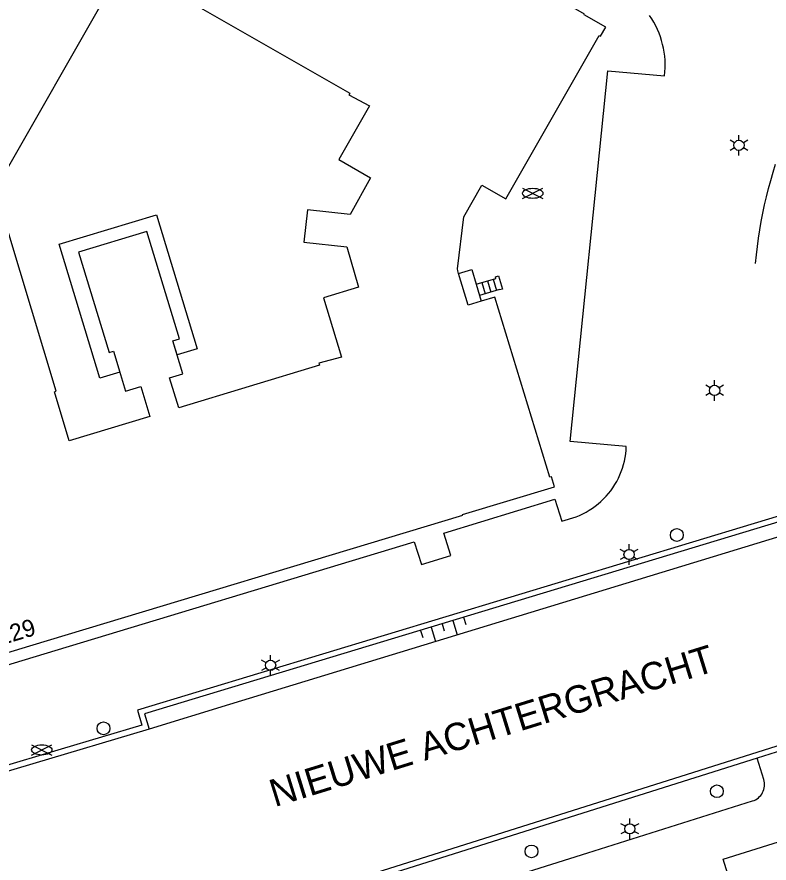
# Model space of a CAD drawing. Extents: x 122462 to 123306, y 485548 to 486417.
# Drawn here: x 122661.2 to 122727, y 486275.7 to 486349.8 of the extents above; entities that cross this region are included whole.
import ezdxf

# ---------------------------------------------------------------- set-up
doc = ezdxf.new("R2010")
doc.units = 0
for name, color, linetype in [('Level 1', 7, 'Continuous'), ('Level 10', 7, 'Continuous'), ('Level 15', 7, 'Continuous'), ('Level 17', 7, 'Continuous'), ('Level 30', 7, 'Continuous'), ('Level 31', 7, 'Continuous'), ('Level 33', 7, 'Continuous'), ('Level 50', 7, 'Continuous'), ('Level 52', 7, 'Continuous'), ('Level 53', 7, 'Continuous'), ('Level 57', 7, 'Continuous'), ('Level 58', 7, 'Continuous'), ('Level 60', 7, 'Continuous')]:
    doc.layers.add(name, color=color, linetype=linetype)

msp = doc.modelspace()

# ---------------------------------------------------------------- linework, layer by layer
at = {"layer": 'Level 1'}
for points in [[(122699.817, 486327.312), (122699.749, 486327.539), (122699.729, 486327.739), (122700.284, 486332.276), (122701.858, 486335.038), (122703.959, 486333.84), (122712.114, 486348.156), (122712.229, 486348.09), (122712.699, 486348.89), (122710.807, 486349.962), (122710.84, 486350.019), (122666.793, 486375.245)], [(122670.497, 486354.444), (122690.291, 486343.11), (122690.207, 486342.963), (122692.022, 486342.005), (122689.355, 486337.307), (122692.119, 486335.704), (122690.347, 486332.49), (122686.599, 486332.897), (122686.294, 486330.053), (122690.041, 486329.638), (122691.06, 486326.112), (122688.005, 486325.193), (122689.573, 486319.986), (122687.594, 486319.457), (122687.646, 486319.284), (122675.334, 486315.567), (122674.54, 486318.195), (122675.69, 486318.542), (122674.822, 486321.415), (122675.391, 486321.587), (122672.55, 486330.998), (122666.579, 486329.195), (122669.237, 486320.39), (122669.616, 486320.505), (122670.667, 486317.025), (122672.014, 486317.432), (122672.808, 486314.804), (122665.752, 486312.674)], [(122665.752, 486312.674), (122664.457, 486316.963), (122664.619, 486317.012), (122659.289, 486334.67), (122669.606, 486352.743)], [(122701.792, 486324.887), (122700.65, 486324.549), (122699.817, 486327.312)], [(122654.824, 486293.037), (122654.979, 486292.519), (122662.302, 486294.73), (122700.189, 486306.17), (122700.175, 486306.219), (122708.219, 486308.64), (122707.959, 486309.519), (122707.814, 486309.477), (122702.979, 486325.239), (122701.792, 486324.887)]]:
    msp.add_lwpolyline(points, dxfattribs=at)
at = {"layer": 'Level 10'}
msp.add_lwpolyline([(122668.431, 486318.142), (122664.882, 486329.891), (122673.401, 486332.464), (122676.949, 486320.715), (122675.194, 486320.185), (122674.822, 486321.415), (122675.391, 486321.587), (122672.55, 486330.998), (122666.579, 486329.195), (122669.237, 486320.39), (122669.616, 486320.505), (122670.171, 486318.668), (122668.431, 486318.142)], dxfattribs=at)
at = {"layer": 'Level 15'}
msp.add_line((122756.891, 486294.683), (122725.93, 486284.893), dxfattribs=at)
for points in [[(122751.923, 486312.872), (122672.34, 486288.76), (122672.74, 486287.44)], [(122731.082, 486307.081), (122671.716, 486289.094), (122672.116, 486287.776), (122665.051, 486285.671), (122641.584, 486278.678), (122641.891, 486277.59), (122640.687, 486277.213)], [(122647.698, 486260.681), (122684.849, 486272.428), (122757.048, 486295.256)], [(122672.74, 486287.44), (122642.199, 486278.339), (122642.372, 486277.724), (122642.388, 486277.64), (122642.389, 486277.555), (122642.376, 486277.47), (122642.348, 486277.389), (122642.308, 486277.314), (122642.255, 486277.247), (122642.191, 486277.19), (122642.119, 486277.145), (122642.04, 486277.112), (122640.835, 486276.735)], [(122725.93, 486284.893), (122710.139, 486279.9), (122647.848, 486260.204), (122647.698, 486260.681)]]:
    msp.add_lwpolyline(points, dxfattribs=at)
at = {"layer": 'Level 17'}
for points in [[(122655.079, 486291.467), (122662.602, 486293.74), (122695.944, 486303.816), (122696.584, 486301.838), (122699.14, 486302.645), (122698.525, 486304.593), (122708.241, 486307.555), (122708.852, 486305.625), (122710.108, 486306.026), (122710.404, 486306.147), (122710.695, 486306.281), (122710.978, 486306.429), (122711.255, 486306.59), (122711.523, 486306.764), (122711.783, 486306.951), (122712.034, 486307.149), (122712.276, 486307.359), (122712.507, 486307.58), (122712.728, 486307.812), (122712.937, 486308.053), (122713.135, 486308.305), (122713.321, 486308.565), (122713.495, 486308.834), (122713.655, 486309.111), (122713.803, 486309.394), (122713.937, 486309.685), (122714.057, 486309.981), (122714.163, 486310.283), (122714.255, 486310.59), (122714.332, 486310.9), (122714.395, 486311.214), (122714.443, 486311.53), (122714.476, 486311.849), (122714.494, 486312.168), (122709.597, 486312.611), (122712.877, 486345.066), (122717.835, 486344.614), (122717.871, 486344.959), (122717.89, 486345.306), (122717.894, 486345.653), (122717.882, 486346), (122717.854, 486346.346), (122717.81, 486346.691), (122717.75, 486347.033), (122717.675, 486347.372), (122717.584, 486347.707), (122717.478, 486348.038), (122717.357, 486348.363), (122717.222, 486348.683), (122717.071, 486348.996), (122716.907, 486349.302), (122716.728, 486349.6), (122716.537, 486349.889)], [(122725.812, 486328.204), (122725.882, 486328.94), (122725.966, 486329.674), (122726.064, 486330.406), (122726.176, 486331.137), (122726.301, 486331.865), (122726.439, 486332.591), (122726.591, 486333.314), (122726.757, 486334.034), (122726.936, 486334.751), (122727.128, 486335.464), (122727.334, 486336.174), (122727.553, 486336.88)], [(122752.269, 486311.737), (122679.763, 486289.585), (122672.74, 486287.44)], [(122647.698, 486260.681), (122647.254, 486260.541), (122648.404, 486256.843), (122711.12, 486276.603), (122725.537, 486281.145), (122725.675, 486281.196), (122725.808, 486281.26), (122725.933, 486281.337), (122726.05, 486281.426), (122726.158, 486281.526), (122726.256, 486281.637), (122726.343, 486281.756), (122726.417, 486281.883), (122726.478, 486282.017), (122726.527, 486282.156), (122726.561, 486282.299), (122726.581, 486282.445), (122726.586, 486282.592), (122726.578, 486282.739), (122726.554, 486282.885), (122726.517, 486283.027), (122725.93, 486284.893)], [(122723.6, 486273.989), (122722.955, 486276.048), (122729.758, 486278.174)]]:
    msp.add_lwpolyline(points, dxfattribs=at)
at = {"layer": 'Level 30'}
for p, q in [((122701.35, 486326.377), (122701.645, 486325.382)), ((122701.645, 486325.382), (122701.792, 486324.887))]:
    msp.add_line(p, q, dxfattribs=at)
msp.add_lwpolyline([(122699.817, 486327.312), (122700.971, 486327.659), (122701.35, 486326.377)], dxfattribs=at)
at = {"layer": 'Level 31'}
msp.add_lwpolyline([(122701.35, 486326.377), (122703.083, 486326.89), (122703.044, 486327.02), (122703.312, 486327.099), (122703.653, 486325.945), (122703.411, 486325.873), (122703.402, 486325.902), (122701.645, 486325.382)], dxfattribs=at)
at = {"layer": 'Level 33'}
for p, q in [((122701.851, 486326.526), (122702.146, 486325.531)), ((122702.352, 486326.675), (122702.647, 486325.68)), ((122702.853, 486326.823), (122703.148, 486325.828))]:
    msp.add_line(p, q, dxfattribs=at)
at = {"layer": 'Level 50'}
for p, q in [((122724.353, 486338.986), (122724.353, 486339.436)), ((122723.963, 486338.761), (122723.573, 486338.986)), ((122725.132, 486338.986), (122724.742, 486338.761)), ((122723.963, 486338.311), (122723.573, 486338.086)), ((122724.353, 486337.636), (122724.353, 486338.086)), ((122725.132, 486338.086), (122724.742, 486338.311)), ((122722.22, 486317.535), (122722.22, 486317.985)), ((122721.83, 486317.31), (122721.44, 486317.535)), ((122722.999, 486317.535), (122722.609, 486317.31)), ((122721.83, 486316.86), (122721.44, 486316.635)), ((122722.22, 486316.185), (122722.22, 486316.635)), ((122722.999, 486316.635), (122722.609, 486316.86)), ((122714.738, 486303.171), (122714.738, 486303.621)), ((122714.348, 486302.946), (122713.958, 486303.171)), ((122715.517, 486303.171), (122715.127, 486302.946)), ((122714.348, 486302.496), (122713.958, 486302.271)), ((122714.738, 486301.821), (122714.738, 486302.271)), ((122715.517, 486302.271), (122715.127, 486302.496)), ((122682.978, 486293.245), (122682.588, 486293.47)), ((122683.368, 486293.47), (122683.368, 486293.92)), ((122684.147, 486293.47), (122683.757, 486293.245)), ((122682.978, 486292.795), (122682.588, 486292.57)), ((122683.368, 486292.12), (122683.368, 486292.57)), ((122684.147, 486292.57), (122683.757, 486292.795)), ((122714.413, 486278.934), (122714.023, 486279.159)), ((122714.803, 486279.159), (122714.803, 486279.609)), ((122715.582, 486279.159), (122715.192, 486278.934)), ((122714.413, 486278.484), (122714.023, 486278.259)), ((122715.582, 486278.259), (122715.192, 486278.484)), ((122714.803, 486277.809), (122714.803, 486278.259))]:
    msp.add_line(p, q, dxfattribs=at)
for centre in [(122724.353, 486338.536), (122722.22, 486317.085), (122714.738, 486302.721), (122683.368, 486293.02), (122714.803, 486278.709)]:
    msp.add_circle(centre, 0.45, dxfattribs=at)
at = {"layer": 'Level 52'}
for p, q in [((122705.42, 486333.891), (122707.201, 486334.781)), ((122705.42, 486334.781), (122707.201, 486333.891)), ((122662.465, 486285.17), (122664.246, 486286.06)), ((122662.465, 486286.06), (122664.246, 486285.17))]:
    msp.add_line(p, q, dxfattribs=at)
for centre in [(122706.31, 486334.334), (122663.355, 486285.613)]:
    msp.add_ellipse(centre, major_axis=(0.89, 0), ratio=0.5, dxfattribs=at)
at = {"layer": 'Level 53'}
for centre in [(122718.914, 486304.426), (122668.752, 486287.501), (122722.417, 486281.999), (122706.2, 486276.732)]:
    msp.add_circle(centre, 0.56, dxfattribs=at)
at = {"layer": 'Level 57'}
for p, q in [((122699.319, 486296.936), (122699.7, 486295.692)), ((122700.262, 486297.225), (122700.452, 486296.602)), ((122697.433, 486296.36), (122697.813, 486295.115)), ((122698.376, 486296.648), (122698.566, 486296.026)), ((122696.49, 486296.072), (122696.68, 486295.45))]:
    msp.add_line(p, q, dxfattribs=at)

# ---------------------------------------------------------------- texts
at = {"layer": 'Level 58'}
msp.add_text('129', height=1.5, rotation=16.80573, dxfattribs=at).set_placement((122659.742, 486294.741))
at = {"layer": 'Level 60'}
msp.add_text('NIEUWE ACHTERGRACHT', height=2.4, rotation=17.18108, dxfattribs=at).set_placement((122683.734, 486280.6))

doc.saveas('drawing.dxf')
